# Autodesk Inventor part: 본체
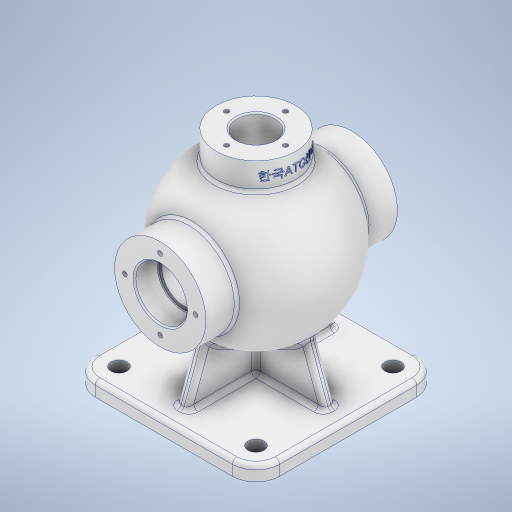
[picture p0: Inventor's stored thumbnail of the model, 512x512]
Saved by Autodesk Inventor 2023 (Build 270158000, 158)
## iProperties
Created: 2023-07
Part Number: 본체
Material: 알루미늄 6061
Document SubType Name: Modeling
Designer: Owner
Density: 2.7 g/cm^3
Appearance: 알루미늄 - 평지
Mass: 1526.72 g
Surface Area: 1173.82 cm^2
Volume: 565.453 cm^3
Author: Owner
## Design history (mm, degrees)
sketch "스케치1"
  geometry: L1 (-62.5, 62.5)-(62.5, 62.5); L2 (62.5, 62.5)-(62.5, -62.5); L3 (62.5, -62.5)-(-62.5, -62.5); L4 (-62.5, -62.5)-(-62.5, 62.5); L5 (-62.5, 62.5)-(62.5, -62.5); L6 (62.5, 62.5)-(-62.5, -62.5); 1 further point
  constraints: 12 end point, 2 midpoint, 2 parallel, 1 horizontal, 1 perpendicular
  dimensions: "d0" = 125 distance of L2.end L3.end; "d1" = 125 distance of L1.end L2.end
extrude "돌출1" new body sketch "스케치1" distance "d2" = 10; taper "d3" = 0 deg
fillet "모깎기1" dims "d4" = 16
fillet "모깎기2" dims "d5" = 3
sketch "스케치2"
  geometry: L1 (7, -62.5)-(0, -62.5) reference; L2 (0, -62.5)-(0, 62.5) reference; L3 (0, 62.5)-(7, 62.5) reference; L4 (10, 59.5)-(10, -59.5) reference; L5 (85, 65)-(85, -65); L6 (85, 65)-(116, 65); L7 (116, 65)-(116, 44.215); L8 (116, -44.215)-(116, -65); L9 (116, -65)-(85, -65); A1 r 3 centre (7, -59.5) between (7, -62.5) and (10, -59.5) reference; A2 r 3 centre (7, 59.5) between (10, 59.5) and (7, 62.5) reference; A3 r 54 centre (85, 0) between (116, -44.215) and (116, 44.215); 3 further points
  constraints: 10 end point, 2 midpoint, 2 perpendicular, 2 point on circle, 2 vertical, 1 centre point, 1 coincident, 1 horizontal, 1 horizontal alignment
  dimensions: "d6" = 130 distance of L5.start L5.end; "d7" = 85 distance between parallel lines of L2 L5; "d8" = 54 radius of A3; "d9" = 62 diameter of L7 L5; "d10" = 62 diameter of L8 L5
revolve "회전1" sketch "스케치2" stored, may be unused: angle "d11" = 90 deg
sketch "스케치3"
  geometry: L1 (7, -62.5)-(0, -62.5) reference; L2 (0, -62.5)-(0, 62.5) reference; L3 (0, 62.5)-(7, 62.5) reference; L4 (10, 59.5)-(10, -59.5) reference; L5 (54, 65)-(116, 65) reference; L6 (116, 65)-(116, 44.215) reference; L7 (116, -44.215)-(116, -65) reference; L8 (116, -65)-(54, -65) reference; L9 (54, -65)-(54, -44.215) reference; L10 (54, 44.215)-(54, 65) reference; L11 (10, 46.5)-(10, -46.5) reference; L12 (10, 50.5)-(55, 34.121); L13 (55, 34.121)-(55, -34.121); L14 (55, -34.121)-(10, -50.5); A1 r 3 centre (7, -59.5) between (7, -62.5) and (10, -59.5) reference; A2 r 3 centre (7, 59.5) between (10, 59.5) and (7, 62.5) reference; A3 r 54 centre (85, 0) between (116, -44.215) and (116, 44.215) reference; A4 r 54 centre (85, 0) between (54, 44.215) and (54, -44.215) reference; 7 further points
  constraints: 6 end point, 2 midpoint, 2 point on line, 1 equal length, 1 horizontal alignment, 1 parallel
  dimensions: "d12" = 20 deg angle of L12 L3; "d13" = 12 vertical distance of L2.end L12.start; "d14" = 55 distance between parallel lines of L2 L13
extrude "돌출2" join sketch "스케치3" stored distance "d15" = 8; taper "d16" = 0 deg
sketch "스케치4"
  geometry: L1 (-59.5, 10)-(-4, 10) reference; L2 (-4, 10)-(-4, 31.148) reference; L3 (4, 31.148)-(4, 10) reference; L4 (4, 10)-(59.5, 10) reference; L5 (62.5, 7)-(62.5, 0) reference; L6 (62.5, 0)-(-62.5, 0) reference; L7 (-62.5, 0)-(-62.5, 7) reference; L8 (-37.385, 46.034)-(-50.5, 10); L9 (-46.5, 10)-(46.5, 10) reference; A1 r 3 centre (-59.5, 7) between (-59.5, 10) and (-62.5, 7) reference; A2 r 3 centre (59.5, 7) between (62.5, 7) and (59.5, 10) reference; A3 r 54 centre (0, 85) between (4, 31.148) and (-4, 31.148) reference; 1 further point
  constraints: 2 end point, 1 point on circle, 1 point on line
  dimensions: "d17" = 20 deg angle of L7 L8; "d18" = 12 distance from line of L7 L8.end
feature "리브1" sketch "스케치4" dims "d19" = 1, "d20" = 8, "d21" = 0, "d22" = 0, "d23" = 1, "d24" = 1
fillet "모깎기3" dims "d25" = 3
fillet "모깎기4" dims "d26" = 3
fillet "모깎기5" dims "d27" = 3
sketch "스케치5"
  geometry: L1 (0, -62.5)-(0, 62.5) reference; L2 (0, 62.5)-(7, 62.5) reference; L3 (10, 59.5)-(10, 52.601) reference; L4 (11.974, 49.782)-(44.231, 38.041) reference; L5 (54, 45.749)-(54, 65) reference; L6 (54, 65)-(116, 65) reference; L7 (116, 65)-(116, 45.749) reference; L8 (116, -45.749)-(116, -65) reference; L9 (116, -65)-(54, -65) reference; L10 (54, -65)-(54, -45.749) reference; L11 (44.231, -38.041)-(11.974, -49.782) reference; L12 (10, -52.601)-(10, -59.5) reference; L13 (7, -62.5)-(0, -62.5) reference; L14 (54, 65)-(116, 65) reference; L15 (85, 65)-(85, -65); L16 (54, -65)-(116, -65) reference; L17 (102.5, 65)-(102.5, 49); L18 (102.5, 49)-(100, 49); L19 (100, 49)-(100, 41.364); L20 (100, -41.364)-(100, -49); L21 (100, -49)-(102.5, -49); L22 (102.5, -49)-(102.5, -65); A1 r 3 centre (7, 59.5) between (10, 59.5) and (7, 62.5) reference; A2 r 3 centre (13, 52.601) between (10, 52.601) and (11.974, 49.782) reference; A3 r 3 centre (45.257, 40.86) between (44.231, 38.041) and (47.349, 38.709) reference; A4 r 54 centre (85, 0) between (52.789, 43.341) and (47.349, 38.709) reference; A5 r 3 centre (51, 45.749) between (52.789, 43.341) and (54, 45.749) reference; A6 r 3 centre (119, 45.749) between (116, 45.749) and (117.211, 43.341) reference; A7 r 54 centre (85, 0) between (117.211, -43.341) and (117.211, 43.341) reference; A8 r 3 centre (119, -45.749) between (117.211, -43.341) and (116, -45.749) reference; A9 r 3 centre (51, -45.749) between (54, -45.749) and (52.789, -43.341) reference; A10 r 54 centre (85, 0) between (47.349, -38.709) and (52.789, -43.341) reference; A11 r 3 centre (45.257, -40.86) between (47.349, -38.709) and (44.231, -38.041) reference; A12 r 3 centre (13, -52.601) between (11.974, -49.782) and (10, -52.601) reference; A13 r 3 centre (7, -59.5) between (7, -62.5) and (10, -59.5) reference; A14 r 44 centre (85, 0) between (100, -41.364) and (100, 41.364); 5 further points
  constraints: 14 end point, 5 perpendicular, 2 equal length, 2 midpoint, 2 point on circle, 2 point on line, 2 vertical, 1 centre point, 1 vertical alignment
  dimensions: "d28" = 44 radius of A14; "d29" = 16 distance of L17.start L17.end; "d30" = 35 diameter of L17 L15; "d31" = 30 diameter of L19 L15
revolve "회전2" sketch "스케치5" stored, may be unused: angle "d32" = 90 deg
node "작업 평면1"
sketch "스케치6"
  geometry: C1 r 27 at (0, 0); C2 r 13 at (0, 0); 1 further point
  constraints: 2 centre point, 2 coincident
  dimensions: "d34" = 54 diameter of C1; "d35" = 26 diameter of C2
extrude "돌출3" join sketch "스케치6" stored distance "d36" = 8; taper "d37" = 0 deg
extrude "돌출4" cut sketch "스케치6" stored distance "d38" = 10; taper "d39" = 0 deg
fillet "모깎기6" dims "d40" = 3
chamfer "모따기1" distance "d41" = 1; stored, may be unused: second distance "d42" = 2, angle "d43" = 45 deg
sketch "스케치7"
  geometry: C1 r 5.5 at (-46.5, 46.5); C2 r 5.5 at (-46.5, -46.5); A1 r 13 centre (-46.5, 46.5) between (-46.5, 59.5) and (-59.5, 46.5) reference; A2 r 13 centre (-46.5, -46.5) between (-59.5, -46.5) and (-46.5, -59.5) reference; 1 further point
  constraints: 2 centre point, 2 coincident, 1 equal radius
  dimensions: "d44" = 11 diameter of C1
extrude "돌출5" cut sketch "스케치7" extent not by distance; stored distance "d45" = 0; taper "d46" = 0 deg
sketch "스케치8"
  geometry: C1 r 31 at (0, 0) reference; 2 further points
  constraints: 1 vertical alignment
  dimensions: "d47" = 24 distance of C1.centre point (0, 24)
hole "구멍1" sketch "스케치8" at (0, 24) diameter "d48" = 3.242; stored, may be unused: countersink angle "d52" = 90 deg, drill point angle "d54" = 118 deg; dims "d49" = 12, "d50" = 4, "d51" = 2, "d53" = 15
sketch "스케치9"
  geometry: C1 r 27 at (0, 0) reference; 1 further point
  constraints: 1 vertical alignment
  dimensions: "d58" = 20 distance of C1.centre point (0, 20)
hole "구멍2" sketch "스케치9" at (0, 20) diameter "d59" = 3.242; stored, may be unused: countersink angle "d63" = 90 deg, drill point angle "d65" = 118 deg; dims "d60" = 9, "d61" = 4, "d62" = 2, "d64" = 11
node "작업 평면2"
sketch "스케치10"
  geometry: L1 (-150, -62.5)-(-150, 62.5) reference; L2 (-150, 62.5)-(-143, 62.5) reference; L3 (-140, 59.5)-(-140, 7) reference; L4 (-137, 4)-(-114.709, 4) reference; L5 (-80.232, 45.749)-(-80.232, 65) reference; L6 (-80.232, 65)-(-49.768, 65) reference; L7 (-49.768, 65)-(-49.768, 45.749) reference; L8 (-49.768, -45.749)-(-49.768, -65) reference; L9 (-49.768, -65)-(-80.232, -65) reference; L10 (-80.232, -65)-(-80.232, -45.749) reference; L11 (-114.709, -4)-(-137, -4) reference; L12 (-140, -7)-(-140, -59.5) reference; L13 (-143, -62.5)-(-150, -62.5) reference; L14 (0, 0)-(-16.534, 0) reference; L15 (0, -27)-(0, 27) reference; C1 r 34.742 at (-65, 0) reference; A1 r 3 centre (-143, 59.5) between (-140, 59.5) and (-143, 62.5) reference; A2 r 3 centre (-137, 7) between (-140, 7) and (-137, 4) reference; A3 r 46.765 centre (-65, 0) between (-82.565, 43.341) and (-111.293, 6.632) reference; A4 r 46.765 centre (-65, 0) between (-19.084, 8.874) and (-47.435, 43.341) reference; A5 r 46.765 centre (-65, 0) between (-47.435, -43.341) and (-19.084, -8.874) reference; A6 r 46.765 centre (-65, 0) between (-111.293, -6.632) and (-82.565, -43.341) reference; A7 r 3 centre (-137, -7) between (-137, -4) and (-140, -7) reference; A8 r 3 centre (-143, -59.5) between (-143, -62.5) and (-140, -59.5) reference; 2 further points
  constraints: 1 horizontal alignment, 9 other
  dimensions: "d69" = 9 distance from line of L15 point (-9, 0)
feature "엠보싱1" sketch "스케치10" dims "d0" = 125, "d1" = 125, "d70" = 0.5, "d71" = 0
fillet "모깎기7" dims "d72" = 0.6
feature "Ǌ耀ǌ耀ǎ耀ǐ耀ǒ耀ǔ耀ǖ耀ǘ耀" dims "d0" = 125, "d1" = 125, "d2" = 10, "d3" = 0, "d4" = 16, "d5" = 3, "d6" = 130, "d7" = 85, "d8" = 54, "d9" = 62, "d10" = 62, "d11" = 90 deg, "d12" = 20 deg, "d13" = 12, "d14" = 55, "d15" = 8, "d16" = 0, "d17" = 20 deg, "d18" = 12, "d19" = 1, "d20" = 8, "d21" = 0, "d22" = 0, "d23" = 1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
node "솔리드1"
mirror "미러1"
mirror "미러2"
pattern_circular "원형 패턴1" dims angle "d56" = 360 deg
mirror "미러3"
pattern_circular "원형 패턴2" dims angle "d67" = 360 deg
node "절단 모서리 투영1"
node "절단 모서리 투영2"
node "절단 모서리 투영3"
node "절단 모서리 투영4"
node "절단 모서리 투영5"
feature "A9D066F2-1C7D-4E18-AEED-F7BC21143FA4" dims "d48" = 3.242, "d49" = 12, "d50" = 4, "d51" = 2, "d52" = 90 deg, "d53" = 15, "d54" = 118 deg
